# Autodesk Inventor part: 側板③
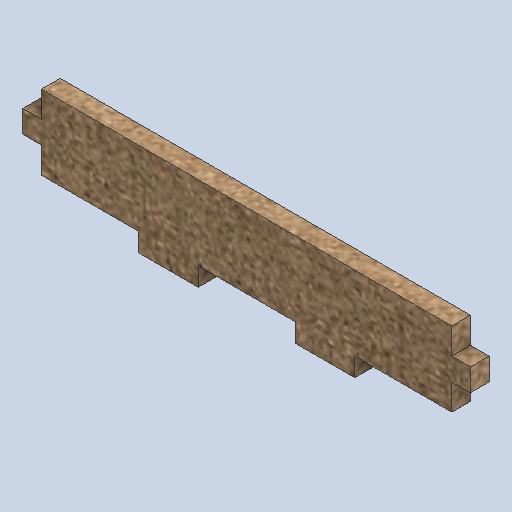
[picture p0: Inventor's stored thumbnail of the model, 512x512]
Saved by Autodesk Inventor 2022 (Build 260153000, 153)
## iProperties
Created: 2024-11
Part Number: 側板③
Material: MDF 中密度繊維ボード
Document SubType Name: Modeling
Designer: shimizu
Density: 0.8 g/cm^3
Appearance: ダンボール - 段ボール紙
Author: shimizu
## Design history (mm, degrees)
sketch "スケッチ1"
  geometry: L1 (-25.358, 1.343)-(29.642, 1.343); L2 (-4.358, -8.657)-(-4.358, -11.157); L3 (-4.358, -11.157)-(-12.358, -11.157); L4 (-12.358, -11.157)-(-12.358, -8.657); L5 (16.642, -8.657)-(16.642, -11.157); L6 (16.642, -11.157)-(8.642, -11.157); L7 (8.642, -11.157)-(8.642, -8.657); L8 (-25.358, -2.157)-(-27.858, -2.157); L9 (-27.858, -2.157)-(-27.858, -5.157); L10 (-27.858, -5.157)-(-25.358, -5.157); L11 (29.642, -2.157)-(32.142, -2.157); L12 (32.142, -2.157)-(32.142, -5.157); L13 (32.142, -5.157)-(29.642, -5.157); L14 (-25.358, -8.657)-(-25.358, -5.157); L15 (-25.358, -2.157)-(-25.358, 1.343); L16 (29.642, 1.343)-(29.642, -2.157); L17 (29.642, -5.157)-(29.642, -8.657); L18 (29.642, -8.657)-(16.642, -8.657); L19 (8.642, -8.657)-(-4.358, -8.657); L20 (-12.358, -8.657)-(-25.358, -8.657); 1 further point
  constraints: 40 end point, 11 parallel, 4 perpendicular, 3 horizontal
  dimensions: "d16" = 13 distance of L17.end L5.start; "d17" = 13 distance of L4.end L14.start; "d18" = 8 distance of L5.end L6.end; "d19" = 8 distance of L2.end L3.end; "d20" = 13 distance of L7.end L2.start; "d21" = 55 distance between parallel lines of L16 L15; "d22" = 60 distance between parallel lines of L12 L9
extrude "押し出し1" new body sketch "スケッチ1" distance "d14" = 2.5; taper "d15" = 0 deg
node "ソリッド1"
